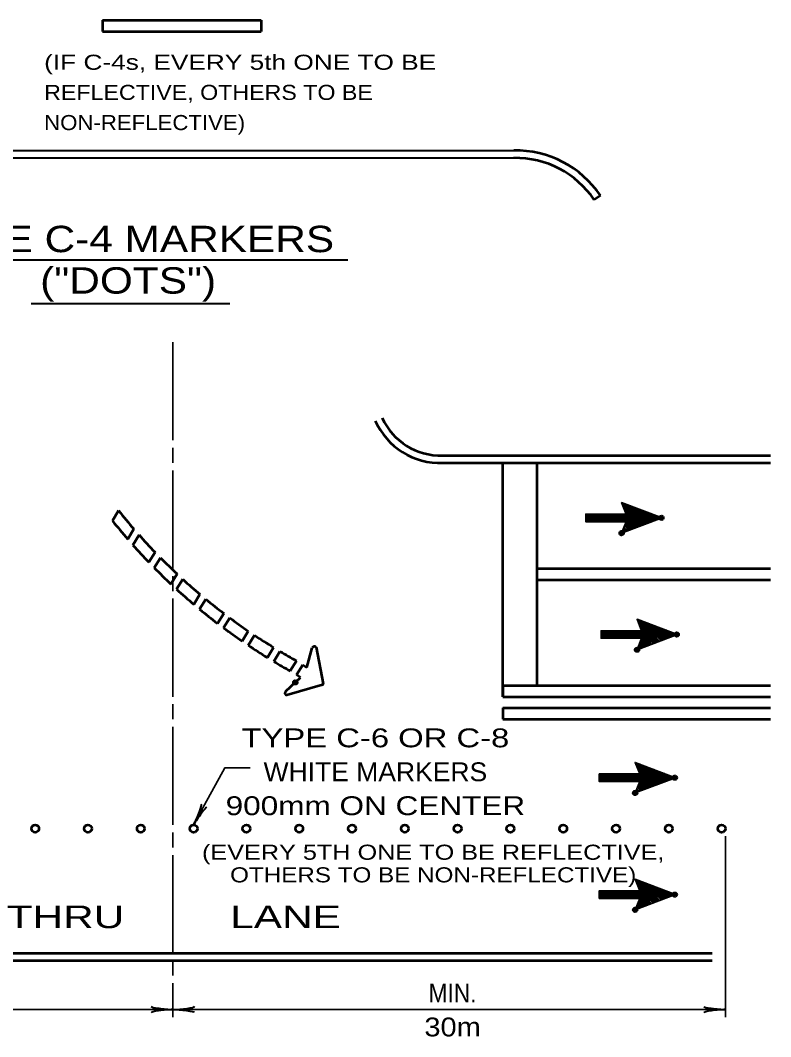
# Model space of a CAD drawing. Extents: x -96 to 617, y -65 to 388.
# Drawn here: x 380.8 to 480.3, y 106.7 to 241.5 of the extents above; entities that cross this region are included whole.
import ezdxf
from ezdxf.enums import TextEntityAlignment as Align

# ---------------------------------------------------------------- set-up
doc = ezdxf.new("R2010")
doc.units = 0
doc.header["$PDMODE"] = 32
doc.header["$PDSIZE"] = 0.5
doc.layers.add('1', color=7, linetype='Continuous', lineweight=53)

msp = doc.modelspace()

# ---------------------------------------------------------------- linework, layer by layer
at = {"layer": '1'}
for p, q in [((391.757, 241.515), (391.757, 240.015)), ((391.757, 241.515), (412.757, 241.515)), ((412.757, 241.515), (412.757, 240.015)), ((391.757, 240.015), (412.757, 240.015)), ((457.757, 218.265), (456.929, 217.705)), ((436.815, 183.817), (480.315, 183.817)), ((436.815, 182.817), (480.315, 182.817)), ((444.815, 151.817), (444.815, 182.817)), ((449.315, 182.817), (449.315, 153.317)), ((393.869, 176.49), (393.05, 175.155)), ((395.894, 174.054), (395.075, 172.719)), ((396.584, 173.267), (395.765, 171.931)), ((398.7, 170.978), (397.881, 169.643)), ((399.42, 170.239), (398.601, 168.904)), ((449.315, 168.817), (480.315, 168.817)), ((401.623, 168.093), (400.804, 166.757)), ((402.371, 167.4), (401.552, 166.065)), ((449.315, 167.317), (480.315, 167.317)), ((404.658, 165.39), (403.839, 164.055)), ((405.433, 164.743), (404.615, 163.407)), ((407.802, 162.866), (406.983, 161.531)), ((408.605, 162.262), (407.786, 160.927)), ((411.053, 160.516), (410.234, 159.181)), ((411.883, 159.956), (411.064, 158.621)), ((414.41, 158.34), (413.592, 157.004)), ((415.266, 157.822), (414.447, 156.487)), ((418.816, 155.706), (419.55, 158.281)), ((420.055, 158.386), (420.991, 153.539)), ((417.435, 156.576), (416.616, 155.241)), ((417.012, 156.812), (417.077, 156.772)), ((416.201, 155.472), (416.194, 155.476)), ((418.277, 156.036), (417.458, 154.701)), ((418.277, 156.036), (418.816, 155.706)), ((416.036, 152.548), (417.998, 154.37)), ((417.998, 154.37), (417.458, 154.701)), ((420.909, 153.404), (416.157, 152.028)), ((444.815, 153.317), (480.315, 153.317)), ((444.815, 153.317), (444.815, 151.817)), ((444.815, 151.817), (480.315, 151.817)), ((444.815, 150.317), (480.315, 150.317)), ((444.815, 150.317), (444.815, 148.817)), ((444.815, 148.817), (480.315, 148.817)), ((329.565, 117.817), (472.565, 117.817)), ((329.565, 116.817), (472.565, 116.817))]:
    msp.add_line(p, q, dxfattribs=at)
at = {"layer": '1', "lineweight": 40}
for p, q in [((335.757, 224.265), (446.257, 224.265)), ((335.757, 223.265), (446.257, 223.265)), ((367.007, 209.768), (424.245, 209.768)), ((382.284, 203.946), (408.61, 203.946))]:
    msp.add_line(p, q, dxfattribs=at)
at = {"layer": '1', "lineweight": 35}
for p, q in [((401.065, 198.817), (401.065, 185.817)), ((401.065, 184.817), (401.065, 182.817)), ((401.065, 181.817), (401.065, 168.817)), ((460.56, 177.455), (463.496, 174.62)), ((460.661, 177.253), (463.395, 174.519)), ((460.762, 177.455), (463.597, 174.62)), ((460.762, 177.05), (463.294, 174.519)), ((460.864, 176.746), (463.192, 174.519)), ((460.965, 177.354), (463.699, 174.721)), ((461.167, 177.354), (463.8, 174.721)), ((461.471, 177.253), (463.901, 174.721)), ((461.674, 177.151), (464.002, 174.823)), ((461.876, 177.05), (464.104, 174.823)), ((462.079, 176.949), (464.205, 174.924)), ((462.382, 176.848), (464.306, 174.924)), ((462.585, 176.746), (464.407, 174.924)), ((462.787, 176.746), (464.509, 175.025)), ((463.091, 176.645), (464.61, 175.025)), ((455.801, 176.038), (461.167, 176.038)), ((455.801, 175.936), (456.712, 175.025)), ((455.801, 175.835), (456.611, 175.025)), ((455.801, 175.734), (456.51, 175.025)), ((455.801, 175.531), (456.307, 175.025)), ((455.801, 175.43), (456.206, 175.025)), ((455.801, 175.228), (456.004, 175.025)), ((455.902, 176.038), (456.915, 175.025)), ((456.004, 176.038), (457.016, 175.025)), ((456.206, 176.038), (457.219, 175.025)), ((456.307, 176.038), (457.32, 175.025)), ((456.51, 176.038), (457.522, 175.025)), ((456.611, 176.038), (457.624, 175.025)), ((456.712, 176.038), (457.725, 175.025)), ((456.915, 176.038), (457.927, 175.025)), ((457.016, 176.038), (458.029, 175.025)), ((457.219, 176.038), (458.231, 175.025)), ((457.32, 176.038), (458.332, 175.025)), ((457.421, 176.038), (458.434, 175.025)), ((457.624, 176.038), (458.636, 175.025)), ((457.725, 176.038), (458.737, 175.025)), ((457.927, 176.038), (458.94, 175.025)), ((458.029, 176.038), (459.041, 175.025)), ((458.231, 176.038), (459.244, 175.025)), ((458.332, 176.038), (459.345, 175.025)), ((458.434, 176.038), (459.446, 175.025)), ((458.636, 176.038), (459.649, 175.025)), ((458.737, 176.038), (459.75, 175.025)), ((458.94, 176.038), (459.952, 175.025)), ((459.041, 176.038), (460.054, 175.025)), ((459.142, 176.038), (460.155, 175.025)), ((459.345, 176.038), (460.357, 175.025)), ((459.446, 176.038), (460.459, 175.025)), ((459.649, 176.038), (460.661, 175.025)), ((459.75, 176.038), (460.762, 175.025)), ((459.851, 176.038), (460.864, 175.025)), ((460.054, 176.038), (461.066, 175.025)), ((460.155, 176.038), (462.079, 174.114)), ((460.357, 176.038), (462.281, 174.114)), ((460.459, 176.038), (462.382, 174.215)), ((460.661, 176.038), (462.484, 174.215)), ((460.762, 176.038), (462.585, 174.215)), ((460.864, 176.038), (462.686, 174.316)), ((460.965, 176.544), (463.091, 174.418)), ((461.066, 176.341), (462.99, 174.418)), ((461.066, 176.038), (462.787, 174.316)), ((461.167, 176.038), (462.889, 174.418)), ((463.294, 176.544), (464.711, 175.126)), ((463.496, 176.443), (464.812, 175.126)), ((463.699, 176.341), (464.914, 175.126)), ((464.002, 176.24), (465.015, 175.228)), ((464.205, 176.139), (465.116, 175.228)), ((464.407, 176.139), (465.217, 175.228)), ((464.61, 176.038), (465.319, 175.329)), ((464.914, 175.936), (465.42, 175.329)), ((465.116, 175.835), (465.521, 175.43)), ((465.319, 175.734), (465.622, 175.43)), ((465.521, 175.633), (465.724, 175.43)), ((455.801, 175.126), (455.902, 175.025)), ((460.762, 174.114), (461.167, 173.709)), ((460.762, 174.013), (461.066, 173.709)), ((460.762, 173.911), (460.965, 173.709)), ((460.864, 174.316), (461.37, 173.81)), ((460.864, 174.215), (461.269, 173.81)), ((460.965, 174.62), (461.674, 173.911)), ((460.965, 174.519), (461.572, 173.911)), ((460.965, 174.418), (461.471, 173.911)), ((461.066, 174.823), (461.876, 174.013)), ((461.066, 174.721), (461.775, 174.013)), ((461.167, 174.924), (461.977, 174.013)), ((460.56, 173.608), (460.661, 173.506)), ((460.661, 173.81), (460.864, 173.608)), ((460.661, 173.709), (460.762, 173.608)), ((401.065, 167.817), (401.065, 165.817)), ((401.065, 164.817), (401.065, 151.817)), ((462.599, 161.986), (465.535, 159.151)), ((462.7, 161.783), (465.434, 159.049)), ((462.802, 161.986), (465.637, 159.151)), ((463.004, 161.885), (465.738, 159.252)), ((463.207, 161.885), (465.839, 159.252)), ((463.51, 161.783), (465.94, 159.252)), ((457.84, 160.568), (463.207, 160.568)), ((457.84, 160.467), (458.752, 159.556)), ((457.942, 160.568), (458.954, 159.556)), ((458.043, 160.568), (459.055, 159.556)), ((458.245, 160.568), (459.258, 159.556)), ((458.347, 160.568), (459.359, 159.556)), ((458.549, 160.568), (459.562, 159.556)), ((458.65, 160.568), (459.663, 159.556)), ((458.752, 160.568), (459.764, 159.556)), ((458.954, 160.568), (459.967, 159.556)), ((459.055, 160.568), (460.068, 159.556)), ((459.258, 160.568), (460.27, 159.556)), ((459.359, 160.568), (460.372, 159.556)), ((459.46, 160.568), (460.473, 159.556)), ((459.663, 160.568), (460.675, 159.556)), ((459.764, 160.568), (460.777, 159.556)), ((459.967, 160.568), (460.979, 159.556)), ((460.068, 160.568), (461.08, 159.556)), ((460.27, 160.568), (461.283, 159.556)), ((460.372, 160.568), (461.384, 159.556)), ((460.473, 160.568), (461.485, 159.556)), ((460.675, 160.568), (461.688, 159.556)), ((460.777, 160.568), (461.789, 159.556)), ((460.979, 160.568), (461.992, 159.556)), ((461.08, 160.568), (462.093, 159.556)), ((461.182, 160.568), (462.194, 159.556)), ((461.384, 160.568), (462.397, 159.556)), ((461.485, 160.568), (462.498, 159.556)), ((461.688, 160.568), (462.7, 159.556)), ((461.789, 160.568), (462.802, 159.556)), ((461.89, 160.568), (462.903, 159.556)), ((462.093, 160.568), (463.105, 159.556)), ((462.194, 160.568), (464.118, 158.644)), ((462.397, 160.568), (464.32, 158.644)), ((462.498, 160.568), (464.422, 158.746)), ((462.7, 160.568), (464.523, 158.746)), ((462.802, 161.581), (465.333, 159.049)), ((462.802, 160.568), (464.624, 158.746)), ((462.903, 161.277), (465.232, 159.049)), ((462.903, 160.568), (464.725, 158.847)), ((463.004, 161.075), (465.13, 158.948)), ((463.105, 160.872), (465.029, 158.948)), ((463.105, 160.568), (464.827, 158.847)), ((463.207, 160.568), (464.928, 158.948)), ((463.713, 161.682), (466.042, 159.353)), ((463.915, 161.581), (466.143, 159.353)), ((464.118, 161.48), (466.244, 159.454)), ((464.422, 161.378), (466.345, 159.454)), ((464.624, 161.277), (466.447, 159.454)), ((464.827, 161.277), (466.548, 159.556)), ((465.13, 161.176), (466.649, 159.556)), ((465.333, 161.075), (466.75, 159.657)), ((465.535, 160.973), (466.852, 159.657)), ((465.738, 160.872), (466.953, 159.657)), ((466.042, 160.771), (467.054, 159.758)), ((466.244, 160.669), (467.155, 159.758)), ((466.447, 160.669), (467.257, 159.758)), ((466.649, 160.568), (467.358, 159.859)), ((466.953, 160.467), (467.459, 159.859)), ((457.84, 160.366), (458.65, 159.556)), ((457.84, 160.264), (458.549, 159.556)), ((457.84, 160.062), (458.347, 159.556)), ((457.84, 159.961), (458.245, 159.556)), ((457.84, 159.758), (458.043, 159.556)), ((457.84, 159.657), (457.942, 159.556)), ((463.004, 159.151), (463.713, 158.442)), ((463.105, 159.353), (463.915, 158.543)), ((463.105, 159.252), (463.814, 158.543)), ((463.207, 159.454), (464.017, 158.543)), ((467.155, 160.366), (467.56, 159.961)), ((467.358, 160.264), (467.662, 159.961)), ((467.56, 160.163), (467.763, 159.961)), ((462.599, 158.138), (462.7, 158.037)), ((462.7, 158.341), (462.903, 158.138)), ((462.7, 158.239), (462.802, 158.138)), ((462.802, 158.644), (463.207, 158.239)), ((462.802, 158.543), (463.105, 158.239)), ((462.802, 158.442), (463.004, 158.239)), ((462.903, 158.847), (463.409, 158.341)), ((462.903, 158.746), (463.308, 158.341)), ((463.004, 159.049), (463.612, 158.442)), ((463.004, 158.948), (463.51, 158.442)), ((416.583, 152.207), (416.583, 152.207)), ((416.586, 152.208), (416.586, 152.208)), ((416.586, 152.208), (416.586, 152.208)), ((416.586, 152.208), (416.586, 152.208)), ((416.586, 152.208), (416.586, 152.208)), ((416.586, 152.208), (416.586, 152.208)), ((401.065, 150.817), (401.065, 148.817)), ((401.065, 147.817), (401.065, 134.817)), ((462.346, 142.991), (465.283, 140.156)), ((462.549, 142.991), (465.384, 140.156)), ((462.751, 142.89), (465.485, 140.257)), ((462.954, 142.89), (465.587, 140.257)), ((457.588, 141.574), (462.954, 141.574)), ((457.689, 141.574), (458.702, 140.561)), ((457.79, 141.574), (458.803, 140.561)), ((457.993, 141.574), (459.005, 140.561)), ((458.094, 141.574), (459.106, 140.561)), ((458.296, 141.574), (459.309, 140.561)), ((458.398, 141.574), (459.41, 140.561)), ((458.499, 141.574), (459.512, 140.561)), ((458.702, 141.574), (459.714, 140.561)), ((458.803, 141.574), (459.815, 140.561)), ((459.005, 141.574), (460.018, 140.561)), ((459.106, 141.574), (460.119, 140.561)), ((459.208, 141.574), (460.22, 140.561)), ((459.41, 141.574), (460.423, 140.561)), ((459.512, 141.574), (460.524, 140.561)), ((459.714, 141.574), (460.726, 140.561)), ((459.815, 141.574), (460.828, 140.561)), ((460.018, 141.574), (461.03, 140.561)), ((460.119, 141.574), (461.131, 140.561)), ((460.22, 141.574), (461.233, 140.561)), ((460.423, 141.574), (461.435, 140.561)), ((460.524, 141.574), (461.536, 140.561)), ((460.726, 141.574), (461.739, 140.561)), ((460.828, 141.574), (461.84, 140.561)), ((460.929, 141.574), (461.941, 140.561)), ((461.131, 141.574), (462.144, 140.561)), ((461.233, 141.574), (462.245, 140.561)), ((461.435, 141.574), (462.448, 140.561)), ((461.536, 141.574), (462.549, 140.561)), ((461.638, 141.574), (462.65, 140.561)), ((461.84, 141.574), (462.853, 140.561)), ((461.941, 141.574), (463.865, 139.65)), ((462.144, 141.574), (464.068, 139.65)), ((462.245, 141.574), (464.169, 139.751)), ((462.448, 142.789), (465.181, 140.055)), ((462.448, 141.574), (464.27, 139.751)), ((462.549, 142.586), (465.08, 140.055)), ((462.549, 141.574), (464.371, 139.751)), ((462.65, 142.282), (464.979, 140.055)), ((462.65, 141.574), (464.473, 139.852)), ((462.751, 142.08), (464.878, 139.954)), ((462.853, 141.877), (464.776, 139.954)), ((462.853, 141.574), (464.574, 139.852)), ((462.954, 141.574), (464.675, 139.954)), ((463.258, 142.789), (465.688, 140.257)), ((463.46, 142.687), (465.789, 140.359)), ((463.663, 142.586), (465.89, 140.359)), ((463.865, 142.485), (465.991, 140.46)), ((464.169, 142.384), (466.093, 140.46)), ((464.371, 142.282), (466.194, 140.46)), ((464.574, 142.282), (466.295, 140.561)), ((464.878, 142.181), (466.397, 140.561)), ((465.08, 142.08), (466.498, 140.662)), ((465.283, 141.979), (466.599, 140.662)), ((465.485, 141.877), (466.7, 140.662)), ((465.789, 141.776), (466.801, 140.764)), ((465.991, 141.675), (466.903, 140.764)), ((466.194, 141.675), (467.004, 140.764)), ((466.397, 141.574), (467.105, 140.865)), ((457.588, 141.472), (458.499, 140.561)), ((457.588, 141.371), (458.398, 140.561)), ((457.588, 141.27), (458.296, 140.561)), ((457.588, 141.067), (458.094, 140.561)), ((457.588, 140.966), (457.993, 140.561)), ((457.588, 140.764), (457.79, 140.561)), ((457.588, 140.662), (457.689, 140.561)), ((462.853, 140.359), (463.663, 139.549)), ((462.853, 140.257), (463.561, 139.549)), ((462.954, 140.46), (463.764, 139.549)), ((466.7, 141.472), (467.207, 140.865)), ((466.903, 141.371), (467.308, 140.966)), ((467.105, 141.27), (467.409, 140.966)), ((467.308, 141.169), (467.51, 140.966)), ((462.346, 139.144), (462.448, 139.042)), ((462.448, 139.346), (462.65, 139.144)), ((462.448, 139.245), (462.549, 139.144)), ((462.549, 139.65), (462.954, 139.245)), ((462.549, 139.549), (462.853, 139.245)), ((462.549, 139.447), (462.751, 139.245)), ((462.65, 139.852), (463.156, 139.346)), ((462.65, 139.751), (463.055, 139.346)), ((462.751, 140.156), (463.46, 139.447)), ((462.751, 140.055), (463.359, 139.447)), ((462.751, 139.954), (463.258, 139.447)), ((401.065, 133.817), (401.065, 131.817)), ((474.315, 133.317), (474.315, 109.317)), ((401.065, 130.817), (401.065, 117.817)), ((462.346, 127.491), (465.283, 124.656)), ((462.448, 127.289), (465.181, 124.555)), ((462.549, 127.491), (465.384, 124.656)), ((462.549, 127.086), (465.08, 124.555)), ((462.65, 126.782), (464.979, 124.555)), ((462.751, 127.39), (465.485, 124.757)), ((462.954, 127.39), (465.587, 124.757)), ((463.258, 127.289), (465.688, 124.757)), ((463.46, 127.187), (465.789, 124.859)), ((463.663, 127.086), (465.89, 124.859)), ((463.865, 126.985), (465.991, 124.96)), ((464.169, 126.884), (466.093, 124.96)), ((464.371, 126.782), (466.194, 124.96)), ((464.574, 126.782), (466.295, 125.061)), ((457.588, 126.074), (462.954, 126.074)), ((457.588, 125.972), (458.499, 125.061)), ((457.588, 125.871), (458.398, 125.061)), ((457.588, 125.77), (458.296, 125.061)), ((457.588, 125.567), (458.094, 125.061)), ((457.588, 125.466), (457.993, 125.061)), ((457.689, 126.074), (458.702, 125.061)), ((457.79, 126.074), (458.803, 125.061)), ((457.993, 126.074), (459.005, 125.061)), ((458.094, 126.074), (459.106, 125.061)), ((458.296, 126.074), (459.309, 125.061)), ((458.398, 126.074), (459.41, 125.061)), ((458.499, 126.074), (459.512, 125.061)), ((458.702, 126.074), (459.714, 125.061)), ((458.803, 126.074), (459.815, 125.061)), ((459.005, 126.074), (460.018, 125.061)), ((459.106, 126.074), (460.119, 125.061)), ((459.208, 126.074), (460.22, 125.061)), ((459.41, 126.074), (460.423, 125.061)), ((459.512, 126.074), (460.524, 125.061)), ((459.714, 126.074), (460.726, 125.061)), ((459.815, 126.074), (460.828, 125.061)), ((460.018, 126.074), (461.03, 125.061)), ((460.119, 126.074), (461.131, 125.061)), ((460.22, 126.074), (461.233, 125.061)), ((460.423, 126.074), (461.435, 125.061)), ((460.524, 126.074), (461.536, 125.061)), ((460.726, 126.074), (461.739, 125.061)), ((460.828, 126.074), (461.84, 125.061)), ((460.929, 126.074), (461.941, 125.061)), ((461.131, 126.074), (462.144, 125.061)), ((461.233, 126.074), (462.245, 125.061)), ((461.435, 126.074), (462.448, 125.061)), ((461.536, 126.074), (462.549, 125.061)), ((461.638, 126.074), (462.65, 125.061)), ((461.84, 126.074), (462.853, 125.061)), ((461.941, 126.074), (463.865, 124.15)), ((462.144, 126.074), (464.068, 124.15)), ((462.245, 126.074), (464.169, 124.251)), ((462.448, 126.074), (464.27, 124.251)), ((462.549, 126.074), (464.371, 124.251)), ((462.65, 126.074), (464.473, 124.352)), ((462.751, 126.58), (464.878, 124.454)), ((462.853, 126.377), (464.776, 124.454)), ((462.853, 126.074), (464.574, 124.352)), ((462.954, 126.074), (464.675, 124.454)), ((464.878, 126.681), (466.397, 125.061)), ((465.08, 126.58), (466.498, 125.162)), ((465.283, 126.479), (466.599, 125.162)), ((465.485, 126.377), (466.7, 125.162)), ((465.789, 126.276), (466.801, 125.264)), ((465.991, 126.175), (466.903, 125.264)), ((466.194, 126.175), (467.004, 125.264)), ((466.397, 126.074), (467.105, 125.365)), ((466.7, 125.972), (467.207, 125.365)), ((466.903, 125.871), (467.308, 125.466)), ((467.105, 125.77), (467.409, 125.466)), ((467.308, 125.669), (467.51, 125.466)), ((457.588, 125.264), (457.79, 125.061)), ((457.588, 125.162), (457.689, 125.061)), ((462.549, 124.15), (462.954, 123.745)), ((462.549, 124.049), (462.853, 123.745)), ((462.65, 124.352), (463.156, 123.846)), ((462.65, 124.251), (463.055, 123.846)), ((462.751, 124.656), (463.46, 123.947)), ((462.751, 124.555), (463.359, 123.947)), ((462.751, 124.454), (463.258, 123.947)), ((462.853, 124.859), (463.663, 124.049)), ((462.853, 124.757), (463.561, 124.049)), ((462.954, 124.96), (463.764, 124.049)), ((462.346, 123.644), (462.448, 123.542)), ((462.448, 123.846), (462.65, 123.644)), ((462.448, 123.745), (462.549, 123.644)), ((462.549, 123.947), (462.751, 123.745)), ((401.065, 116.817), (401.065, 114.817)), ((401.065, 113.817), (401.065, 109.317))]:
    msp.add_line(p, q, dxfattribs=at)
for points in [[(465.926, 175.531), (460.56, 173.506), (461.167, 175.025), (455.801, 175.025), (455.801, 176.038), (461.167, 176.038), (460.56, 177.556)], [(467.965, 160.062), (462.599, 158.037), (463.207, 159.556), (457.84, 159.556), (457.84, 160.568), (463.207, 160.568), (462.599, 162.087)], [(467.713, 141.067), (462.346, 139.042), (462.954, 140.561), (457.588, 140.561), (457.588, 141.574), (462.954, 141.574), (462.346, 143.092)], [(467.713, 125.567), (462.346, 123.542), (462.954, 125.061), (457.588, 125.061), (457.588, 126.074), (462.954, 126.074), (462.346, 127.592)]]:
    msp.add_lwpolyline(points, close=True, dxfattribs=at)
for points in [[(461.167, 175.025), (455.801, 175.025), (455.801, 176.038)], [(463.207, 159.556), (457.84, 159.556), (457.84, 160.568)], [(403.815, 134.817), (407.976, 142.383), (411.328, 142.383)], [(462.954, 140.561), (457.588, 140.561), (457.588, 141.574)], [(462.954, 125.061), (457.588, 125.061), (457.588, 126.074)], [(326.315, 110.317), (401.065, 110.317), (474.315, 110.317)]]:
    msp.add_lwpolyline(points, dxfattribs=at)
at = {"layer": '1'}
for centre in [(382.815, 134.317), (389.815, 134.317), (396.815, 134.317), (403.815, 134.317), (410.815, 134.317), (417.815, 134.317), (424.815, 134.317), (431.815, 134.317), (438.815, 134.317), (445.815, 134.317), (452.815, 134.317), (459.815, 134.317), (466.815, 134.317), (473.815, 134.317)]:
    msp.add_circle(centre, 0.5, dxfattribs=at)
for centre, radius, start, end in [((446.46, 210.632), 13.634, 34.04361, 90.85077), ((446.46, 210.632), 12.634, 34.04361, 90.85077), ((436.505, 192.223), 8.411, 203.88352, 272.10571), ((436.505, 192.223), 9.411, 203.88352, 272.10571), ((455.873, 225.963), 79.322, 218.58592, 220.87455), ((455.054, 224.627), 79.322, 218.58592, 220.87455), ((455.873, 225.963), 79.322, 221.63086, 223.88222), ((455.054, 224.627), 79.322, 221.63086, 223.88222), ((455.873, 225.963), 79.322, 224.62745, 226.84927), ((455.054, 224.627), 79.322, 224.62745, 226.84927), ((455.873, 225.963), 79.322, 227.58578, 229.78496), ((455.054, 224.627), 79.322, 227.58578, 229.78496), ((455.873, 225.963), 79.322, 230.51498, 232.69777), ((455.054, 224.627), 79.322, 230.51498, 232.69772), ((455.873, 225.963), 79.322, 233.42332, 235.59562), ((455.054, 224.627), 79.322, 233.42335, 235.59562), ((455.873, 225.963), 79.322, 236.31863, 238.48608), ((455.054, 224.627), 79.322, 236.31863, 238.48608), ((455.873, 225.963), 79.322, 239.20843, 241.01494), ((419.842, 158.144), 0.322, 48.66733, 154.9259), ((455.054, 224.627), 79.322, 239.20843, 241.01497), ((416.213, 152.315), 0.292, 127.16135, 259.0678), ((420.886, 153.515), 0.118, 266.3777, 34.92723)]:
    msp.add_arc(centre, radius, start, end, dxfattribs=at)
at = {"layer": '1', "lineweight": 40}
for centre, major_axis, ratio, start_param, end_param in [((404.098, 135.907), (-0.724, -1.64), 0.122415, 0.8963533, 3.1415927), ((404.54, 135.697), (1, 1.454), 0.07063, 6.2823074, 8.5597026), ((399.944, 110.529), (1.756, -0.176), 0.07063, 3.1407148, 5.41811), ((399.944, 110.529), (1.756, -0.176), 0.07063, 3.1407148, 5.41811), ((402.156, 110.594), (-1.786, -0.156), 0.122415, 0.8963533, 3.1415927), ((402.156, 110.594), (-1.786, -0.156), 0.122415, 0.8963533, 3.1415927), ((473.194, 110.529), (1.756, -0.176), 0.07063, 3.1407148, 5.41811), ((399.973, 110.041), (1.786, 0.156), 0.122415, 0.8963533, 3.1415927), ((399.973, 110.041), (1.786, 0.156), 0.122415, 0.8963533, 3.1415927), ((402.185, 110.106), (-1.756, 0.176), 0.07063, 3.1407148, 5.41811), ((402.185, 110.106), (-1.756, 0.176), 0.07063, 3.1407148, 5.41811), ((473.223, 110.041), (1.786, 0.156), 0.122415, 0.8963533, 3.1415927)]:
    msp.add_ellipse(centre, major_axis=major_axis, ratio=ratio, start_param=start_param, end_param=end_param, dxfattribs=at)
at = {"layer": '1'}
for p in [(465.825, 175.531), (460.56, 173.506), (467.864, 160.062), (462.599, 158.037), (417.292, 153.704), (467.611, 141.067), (462.346, 139.042), (467.611, 125.567), (462.346, 123.542)]:
    msp.add_point(p, dxfattribs=at)

# ---------------------------------------------------------------- texts
for s, width, p in [('(IF C-4s, EVERY 5th ONE TO BE', 1.3, (384.001, 234.956)), ('REFLECTIVE, OTHERS TO BE', 1.15, (384.001, 230.956)), ('NON-REFLECTIVE)', 1.1, (384.001, 226.956))]:
    msp.add_text(s, height=2, dxfattribs=dict(at, width=width)).set_placement(p)
for s, height, width, p in [('TYPE C-4 MARKERS', 3.5, 1.2, (395.137, 210.768)), ('("DOTS")', 3.5, 1.2, (395.137, 205.268)), ('TYPE C-6 OR C-8', 2.5, 1.3, (427.914, 145.103)), ('WHITE MARKERS', 2.5, 1.05, (427.914, 140.603)), ('900mm ON CENTER', 2.5, 1.25, (427.914, 136.103)), ('(EVERY 5TH ONE TO BE REFLECTIVE,', 2, 1.25, (435.58, 130.187)), ('OTHERS TO BE NON-REFLECTIVE)', 2, 1.2, (435.58, 127.187)), ('THRU         LANE', 3, 1.4, (401.183, 121.119)), ('MIN.', 2.5, 0.9, (438.148, 111.26)), ('30m', 2.5, 1.15, (438.148, 106.76))]:
    msp.add_text(s, height=height, dxfattribs=dict(at, width=width)).set_placement(p, align=Align.CENTER)

doc.saveas('drawing.dxf')
